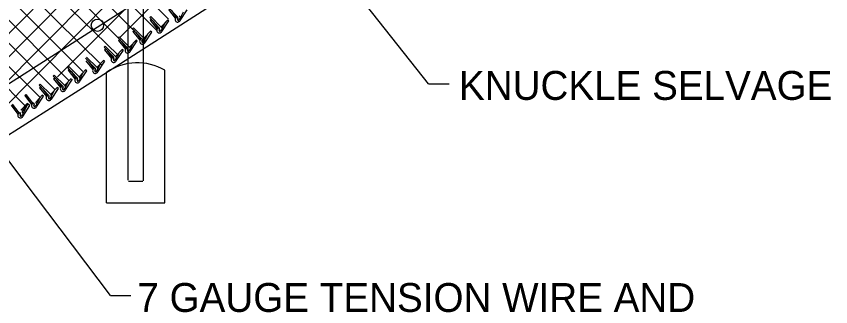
# Model space of a CAD drawing. Extents: x 0 to 2.85, y -0.1 to 1.83.
# Drawn here: x 1.7594 to 2.0414, y 1.3819 to 1.4824 of the extents above; entities that cross this region are included whole.
import ezdxf

# ---------------------------------------------------------------- set-up
doc = ezdxf.new("R2010")
doc.units = 0
for name, color, linetype in [('CT_Dimensions', 7, 'Continuous'), ('sb_Chainlink Fence', 7, 'Continuous'), ('sb_Earth', 7, 'Continuous'), ('sb_Existing Concrete', 7, 'Continuous'), ('sb_Existing Structural Steel', 7, 'Continuous')]:
    doc.layers.add(name, color=color, linetype=linetype)

msp = doc.modelspace()

# ---------------------------------------------------------------- linework, layer by layer
at = {"layer": 'CT_Dimensions'}
for p, q in [((1.9021660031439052, 1.4590312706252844), (1.8609873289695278, 1.5110686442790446)), ((1.9021660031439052, 1.4590312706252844), (1.9092764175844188, 1.4590312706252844)), ((1.7920044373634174, 1.3858294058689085), (1.74611189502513, 1.4465451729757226)), ((1.7920044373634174, 1.3858294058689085), (1.7991148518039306, 1.3858294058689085))]:
    msp.add_line(p, q, dxfattribs=at)
at = {"layer": 'sb_Chainlink Fence'}
for p, q in [((1.689092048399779, 1.4081735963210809), (1.9986754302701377, 1.720458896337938)), ((1.713665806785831, 1.4249653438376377), (1.998677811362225, 1.7124648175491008)), ((1.7334939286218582, 1.436970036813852), (1.9948211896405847, 1.700578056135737)), ((1.7532122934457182, 1.448864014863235), (1.998630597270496, 1.6964242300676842)), ((1.7736272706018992, 1.4614473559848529), (1.9971689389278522, 1.6849890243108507)), ((1.7950888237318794, 1.474947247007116), (1.9974037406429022, 1.6772621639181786)), ((1.7349460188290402, 1.558625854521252), (1.8121597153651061, 1.481412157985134)), ((1.7293783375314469, 1.5562318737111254), (1.8082147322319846, 1.4773954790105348)), ((1.727580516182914, 1.5500680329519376), (1.7997229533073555, 1.477925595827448)), ((1.7215126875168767, 1.548174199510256), (1.7947317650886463, 1.4749551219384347)), ((1.716204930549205, 1.5455202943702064), (1.7947645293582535, 1.4688543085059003)), ((1.705270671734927, 1.5405312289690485), (1.774946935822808, 1.4708549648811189)), ((1.7123356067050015, 1.5414279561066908), (1.7889703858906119, 1.4655716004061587)), ((1.7001417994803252, 1.5376984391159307), (1.7776412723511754, 1.4601989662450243)), ((1.6951924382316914, 1.5346861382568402), (1.7728832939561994, 1.4569952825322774)), ((1.6907662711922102, 1.5311506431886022), (1.7605489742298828, 1.4613679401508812)), ((1.685895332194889, 1.5280599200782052), (1.7624942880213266, 1.4514609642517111)), ((1.8151488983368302, 1.4823272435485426), (1.8119270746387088, 1.4857572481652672)), ((1.8120604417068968, 1.484831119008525), (1.8144700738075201, 1.4817938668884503)), ((1.813099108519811, 1.4844979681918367), (1.8147937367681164, 1.482186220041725)), ((1.8161694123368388, 1.4809619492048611), (1.8186097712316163, 1.4846482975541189)), ((1.8164483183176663, 1.4824171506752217), (1.8172615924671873, 1.4839678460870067)), ((1.8055949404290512, 1.4819829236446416), (1.8059911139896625, 1.4823411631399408)), ((1.808816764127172, 1.4785529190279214), (1.8055949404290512, 1.4819829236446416)), ((1.8057283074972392, 1.481056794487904), (1.8061244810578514, 1.4814150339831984)), ((1.8057283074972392, 1.481056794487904), (1.8081379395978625, 1.4780195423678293)), ((1.8096146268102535, 1.4786945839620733), (1.8059911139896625, 1.4823411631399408)), ((1.8118319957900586, 1.4811791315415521), (1.8096597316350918, 1.4788440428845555)), ((1.8118319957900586, 1.4811791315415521), (1.8096735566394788, 1.478857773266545)), ((1.8098372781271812, 1.4771876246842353), (1.812277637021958, 1.4808739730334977)), ((1.812277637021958, 1.4808739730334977), (1.8118319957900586, 1.4811791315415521)), ((1.8144815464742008, 1.4817691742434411), (1.81445043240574, 1.4816963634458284)), ((1.8145180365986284, 1.4818372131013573), (1.8144815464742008, 1.4817691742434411)), ((1.815007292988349, 1.4824139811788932), (1.8145155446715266, 1.4818351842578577)), ((1.8150138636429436, 1.4824229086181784), (1.8145180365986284, 1.4818372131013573)), ((1.8151961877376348, 1.4814335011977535), (1.8153601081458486, 1.4817876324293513)), ((1.815359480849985, 1.481775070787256), (1.8151965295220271, 1.4814415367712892)), ((1.8161225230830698, 1.4816307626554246), (1.8156768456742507, 1.481104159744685)), ((1.815717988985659, 1.4811474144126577), (1.8161225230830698, 1.4816307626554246)), ((1.7996496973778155, 1.478102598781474), (1.800045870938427, 1.4784608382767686)), ((1.8028715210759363, 1.474672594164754), (1.7996496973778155, 1.478102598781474)), ((1.8036693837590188, 1.4748142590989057), (1.800045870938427, 1.4784608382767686)), ((1.8067669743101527, 1.4807236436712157), (1.8084616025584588, 1.4784118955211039)), ((1.8081494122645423, 1.47799484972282), (1.8081182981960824, 1.4779220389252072)), ((1.80818590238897, 1.478062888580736), (1.8081494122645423, 1.47799484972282)), ((1.8086751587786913, 1.4786396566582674), (1.8081834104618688, 1.4780608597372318)), ((1.8086817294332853, 1.4786485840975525), (1.80818590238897, 1.478062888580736)), ((1.8088640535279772, 1.4776591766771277), (1.8090279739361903, 1.4780133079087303)), ((1.8090273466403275, 1.47800074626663), (1.8088643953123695, 1.4776672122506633)), ((1.8101161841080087, 1.478642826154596), (1.8109294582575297, 1.4801935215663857)), ((1.7946264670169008, 1.4750215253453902), (1.7950226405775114, 1.4753797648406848)), ((1.798646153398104, 1.471733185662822), (1.7950226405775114, 1.4753797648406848)), ((1.7997830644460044, 1.4771764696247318), (1.800179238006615, 1.4775347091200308)), ((1.7997830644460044, 1.4771764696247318), (1.8021926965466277, 1.474139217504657)), ((1.800821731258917, 1.476843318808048), (1.8025163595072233, 1.4745315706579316)), ((1.8058867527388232, 1.4772988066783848), (1.8037144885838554, 1.4749637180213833)), ((1.8058867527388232, 1.4772988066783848), (1.8037283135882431, 1.4749774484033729)), ((1.8038920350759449, 1.4733072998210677), (1.8063323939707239, 1.4769936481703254)), ((1.8041709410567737, 1.4747625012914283), (1.8049842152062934, 1.4763131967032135)), ((1.8063323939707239, 1.4769936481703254), (1.8058867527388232, 1.4772988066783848)), ((1.8097903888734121, 1.4778564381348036), (1.8093447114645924, 1.4773298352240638)), ((1.8093858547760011, 1.4773730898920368), (1.8097903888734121, 1.4778564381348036)), ((1.7978482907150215, 1.4715915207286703), (1.7946264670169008, 1.4750215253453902)), ((1.794759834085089, 1.474095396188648), (1.7951560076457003, 1.4744536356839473)), ((1.794759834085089, 1.474095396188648), (1.797169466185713, 1.4710581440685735)), ((1.7957985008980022, 1.4737622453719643), (1.7974931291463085, 1.4714504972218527)), ((1.8008635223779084, 1.474217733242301), (1.7986912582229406, 1.4718826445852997)), ((1.8008635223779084, 1.474217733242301), (1.7987050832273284, 1.4718963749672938)), ((1.7988688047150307, 1.4702262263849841), (1.801309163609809, 1.473912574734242)), ((1.7991477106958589, 1.4716814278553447), (1.7999609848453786, 1.47323212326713)), ((1.801309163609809, 1.473912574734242), (1.8008635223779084, 1.474217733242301)), ((1.8022041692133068, 1.4741145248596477), (1.802173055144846, 1.4740417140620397)), ((1.8022406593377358, 1.4741825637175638), (1.8022041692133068, 1.4741145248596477)), ((1.802729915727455, 1.4747593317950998), (1.8022381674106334, 1.4741805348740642)), ((1.802736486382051, 1.4747682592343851), (1.8022406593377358, 1.4741825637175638)), ((1.8029188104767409, 1.4737788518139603), (1.8030827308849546, 1.474132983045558)), ((1.8030821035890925, 1.4741204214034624), (1.8029191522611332, 1.4737868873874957)), ((1.8038451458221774, 1.4739761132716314), (1.8033994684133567, 1.4734495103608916)), ((1.8034406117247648, 1.4734927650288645), (1.8038451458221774, 1.4739761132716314)), ((1.7740540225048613, 1.4717105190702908), (1.782411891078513, 1.4633526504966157)), ((1.7897958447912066, 1.4717888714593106), (1.7901920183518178, 1.4721471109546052)), ((1.793017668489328, 1.4683588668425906), (1.7897958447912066, 1.4717888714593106)), ((1.7899292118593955, 1.4708627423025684), (1.7903253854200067, 1.4712209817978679)), ((1.7899292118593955, 1.4708627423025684), (1.7923388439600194, 1.4678254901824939)), ((1.7938155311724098, 1.4685005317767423), (1.7901920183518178, 1.4721471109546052)), ((1.790967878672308, 1.4705295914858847), (1.7926625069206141, 1.468217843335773)), ((1.7960329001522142, 1.4709850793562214), (1.793860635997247, 1.46864999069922)), ((1.7960329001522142, 1.4709850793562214), (1.7938744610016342, 1.4686637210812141)), ((1.7940381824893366, 1.4669935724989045), (1.796478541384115, 1.4706799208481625)), ((1.7943170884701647, 1.468448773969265), (1.795130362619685, 1.469999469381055)), ((1.796478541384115, 1.4706799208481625), (1.7960329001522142, 1.4709850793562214)), ((1.797180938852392, 1.4710334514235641), (1.7971498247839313, 1.470960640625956)), ((1.797217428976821, 1.47110149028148), (1.797180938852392, 1.4710334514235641)), ((1.7977066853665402, 1.471678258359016), (1.797214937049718, 1.4710994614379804)), ((1.7977132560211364, 1.4716871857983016), (1.797217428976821, 1.47110149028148)), ((1.797895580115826, 1.4706977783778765), (1.7980595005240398, 1.4710519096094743)), ((1.7980588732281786, 1.4710393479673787), (1.7978959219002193, 1.470705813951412)), ((1.7988219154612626, 1.4708950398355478), (1.798376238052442, 1.470368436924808)), ((1.7984173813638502, 1.4704116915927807), (1.7988219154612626, 1.4708950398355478)), ((1.7865935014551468, 1.4645487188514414), (1.7833716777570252, 1.467978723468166)), ((1.7835050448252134, 1.4670525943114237), (1.7859146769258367, 1.464015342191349)), ((1.7873913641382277, 1.4646903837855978), (1.7837678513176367, 1.4683369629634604)), ((1.7845437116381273, 1.4667194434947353), (1.786238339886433, 1.4644076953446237)), ((1.7896087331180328, 1.4671749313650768), (1.7874364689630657, 1.4648398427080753)), ((1.7896087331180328, 1.4671749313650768), (1.7874502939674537, 1.4648535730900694)), ((1.7876140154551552, 1.463183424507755), (1.7900543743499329, 1.4668697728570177)), ((1.7900543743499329, 1.4668697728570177), (1.7896087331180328, 1.4671749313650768)), ((1.7923503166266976, 1.4678007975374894), (1.7923192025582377, 1.4677279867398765)), ((1.7923868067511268, 1.4678688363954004), (1.7923503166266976, 1.4678007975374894)), ((1.792876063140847, 1.4684456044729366), (1.7923843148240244, 1.4678668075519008)), ((1.792882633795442, 1.468454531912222), (1.7923868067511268, 1.4678688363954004)), ((1.7930649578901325, 1.467465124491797), (1.7932288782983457, 1.4678192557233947)), ((1.7932282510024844, 1.467806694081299), (1.793065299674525, 1.4674731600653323)), ((1.7939912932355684, 1.4676623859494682), (1.7935456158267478, 1.467135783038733)), ((1.7935867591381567, 1.467179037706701), (1.7939912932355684, 1.4676623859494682)), ((1.7771850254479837, 1.4647243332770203), (1.7775811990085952, 1.465082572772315)), ((1.7804068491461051, 1.4612943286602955), (1.7771850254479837, 1.4647243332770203)), ((1.7773183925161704, 1.463798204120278), (1.777714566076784, 1.4641564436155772)), ((1.7812047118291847, 1.461435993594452), (1.7775811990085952, 1.465082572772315)), ((1.7834220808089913, 1.463920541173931), (1.7812498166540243, 1.4615854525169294)), ((1.7834220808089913, 1.463920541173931), (1.781263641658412, 1.4615991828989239)), ((1.7838677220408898, 1.4636153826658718), (1.7834220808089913, 1.463920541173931)), ((1.7859261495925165, 1.4639906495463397), (1.7858950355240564, 1.463917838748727)), ((1.7859626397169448, 1.464058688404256), (1.7859261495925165, 1.4639906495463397)), ((1.7864518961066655, 1.4646354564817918), (1.785960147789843, 1.4640566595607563)), ((1.78645846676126, 1.4646443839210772), (1.7859626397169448, 1.464058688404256)), ((1.7866407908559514, 1.4636549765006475), (1.7868047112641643, 1.46400910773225)), ((1.7868040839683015, 1.4639965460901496), (1.7866411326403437, 1.4636630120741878)), ((1.7875671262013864, 1.4638522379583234), (1.7871214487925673, 1.4633256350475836)), ((1.7871625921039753, 1.4633688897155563), (1.7875671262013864, 1.4638522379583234)), ((1.7878929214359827, 1.4646386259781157), (1.7887061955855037, 1.4661893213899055)), ((1.7676168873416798, 1.4542955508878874), (1.760468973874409, 1.4614889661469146)), ((1.7721778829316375, 1.4617438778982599), (1.772574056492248, 1.4621021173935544)), ((1.7753997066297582, 1.45831387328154), (1.7721778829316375, 1.4617438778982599)), ((1.7723112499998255, 1.4608177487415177), (1.7727074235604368, 1.4611759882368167)), ((1.7761975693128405, 1.4584555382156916), (1.772574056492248, 1.4621021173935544)), ((1.7773183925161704, 1.463798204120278), (1.7797280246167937, 1.4607609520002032)), ((1.7783570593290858, 1.4634650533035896), (1.7800516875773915, 1.461153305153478)), ((1.780265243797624, 1.4613810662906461), (1.7797734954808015, 1.4608022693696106)), ((1.7802718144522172, 1.4613899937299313), (1.7797759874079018, 1.4608042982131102)), ((1.7814273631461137, 1.4599290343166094), (1.7838677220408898, 1.4636153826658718)), ((1.7817062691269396, 1.46138423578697), (1.7825195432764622, 1.4629349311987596)), ((1.7672997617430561, 1.4586065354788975), (1.7676959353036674, 1.458964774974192)), ((1.7705215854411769, 1.4551765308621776), (1.7672997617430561, 1.4586065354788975)), ((1.7713194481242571, 1.4553181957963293), (1.7676959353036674, 1.458964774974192)), ((1.7723112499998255, 1.4608177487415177), (1.7747208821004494, 1.4577804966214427)), ((1.773349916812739, 1.460484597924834), (1.775044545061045, 1.4581728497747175)), ((1.775258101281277, 1.4584006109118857), (1.7747663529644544, 1.45782181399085)), ((1.775264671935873, 1.458409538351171), (1.7747688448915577, 1.4578238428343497)), ((1.7784149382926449, 1.4609400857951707), (1.7762426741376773, 1.458604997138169)), ((1.7784149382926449, 1.4609400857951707), (1.776256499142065, 1.4586187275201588)), ((1.7764202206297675, 1.4569485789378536), (1.7788605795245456, 1.4606349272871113)), ((1.7766991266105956, 1.4584037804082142), (1.777512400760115, 1.4599544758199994)), ((1.7797394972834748, 1.4607362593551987), (1.779708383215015, 1.4606634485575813)), ((1.7797759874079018, 1.4608042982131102), (1.7797394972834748, 1.4607362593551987)), ((1.7804541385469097, 1.4604005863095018), (1.7806180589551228, 1.4607547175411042)), ((1.7806174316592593, 1.4607421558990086), (1.7804544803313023, 1.4604086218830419)), ((1.7813804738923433, 1.4605978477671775), (1.7809347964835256, 1.4600712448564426)), ((1.7809759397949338, 1.4601144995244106), (1.7813804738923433, 1.4605978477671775)), ((1.7674331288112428, 1.4576804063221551), (1.7678293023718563, 1.4580386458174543)), ((1.7674331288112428, 1.4576804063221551), (1.769842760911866, 1.4546431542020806)), ((1.7684717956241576, 1.4573472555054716), (1.7701664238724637, 1.4550355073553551)), ((1.7735368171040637, 1.4578027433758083), (1.7713645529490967, 1.4554676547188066)), ((1.7735368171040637, 1.4578027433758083), (1.7713783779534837, 1.455481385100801)), ((1.7715420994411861, 1.4538112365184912), (1.7739824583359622, 1.457497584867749)), ((1.771821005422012, 1.4552664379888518), (1.7726342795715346, 1.456817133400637)), ((1.7739824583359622, 1.457497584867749), (1.7735368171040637, 1.4578027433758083)), ((1.7747323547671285, 1.4577558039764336), (1.7747012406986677, 1.4576829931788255)), ((1.7747688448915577, 1.4578238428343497), (1.7747323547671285, 1.4577558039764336)), ((1.7747920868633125, 1.4577099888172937), (1.7747609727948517, 1.457637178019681)), ((1.7748285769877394, 1.4577780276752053), (1.7747920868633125, 1.4577099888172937)), ((1.7754469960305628, 1.4574201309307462), (1.7756109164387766, 1.457774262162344)), ((1.775610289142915, 1.4577617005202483), (1.7754473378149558, 1.4574281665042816)), ((1.776373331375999, 1.4576173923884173), (1.7759276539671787, 1.4570907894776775)), ((1.7759687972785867, 1.4571340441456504), (1.776373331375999, 1.4576173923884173)), ((1.76230612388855, 1.4549912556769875), (1.7627022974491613, 1.4553494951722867)), ((1.76230612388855, 1.4549912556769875), (1.764715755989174, 1.4519540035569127)), ((1.7627022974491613, 1.4553494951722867), (1.7650394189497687, 1.4523463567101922)), ((1.7652529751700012, 1.4525741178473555), (1.7647612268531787, 1.4519953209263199)), ((1.7652595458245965, 1.4525830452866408), (1.7647637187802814, 1.4519973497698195)), ((1.7684098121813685, 1.4551135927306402), (1.7662375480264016, 1.452778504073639)), ((1.7684098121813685, 1.4551135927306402), (1.7662513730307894, 1.4527922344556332)), ((1.766415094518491, 1.4511220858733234), (1.7688554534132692, 1.4548084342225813)), ((1.76669400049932, 1.4525772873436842), (1.7675072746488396, 1.4541279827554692)), ((1.7688554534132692, 1.4548084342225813), (1.7684098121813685, 1.4551135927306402)), ((1.7696650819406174, 1.4550208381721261), (1.7696339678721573, 1.4549480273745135)), ((1.7697015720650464, 1.4550888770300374), (1.7696650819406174, 1.4550208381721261)), ((1.7698542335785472, 1.4546184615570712), (1.7698231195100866, 1.4545456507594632)), ((1.7698907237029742, 1.4546865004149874), (1.7698542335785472, 1.4546184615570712)), ((1.7703799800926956, 1.4552632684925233), (1.769888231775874, 1.4546844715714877)), ((1.7703865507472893, 1.4552721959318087), (1.7698907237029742, 1.4546865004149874)), ((1.770568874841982, 1.4542827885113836), (1.7707327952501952, 1.4546369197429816)), ((1.7707321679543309, 1.4546243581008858), (1.7705692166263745, 1.454290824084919)), ((1.7714952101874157, 1.4544800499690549), (1.7710495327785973, 1.453953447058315)), ((1.7710906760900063, 1.4539967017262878), (1.7714952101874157, 1.4544800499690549)), ((1.7575715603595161, 1.451634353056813), (1.75998119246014, 1.4485971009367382)), ((1.757967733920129, 1.4519925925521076), (1.7603048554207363, 1.4489894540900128)), ((1.763197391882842, 1.4522746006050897), (1.761025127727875, 1.4499395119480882)), ((1.763197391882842, 1.4522746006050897), (1.761038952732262, 1.4499532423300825)), ((1.7615145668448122, 1.4494327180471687), (1.7633168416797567, 1.4521551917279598)), ((1.7616805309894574, 1.447765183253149), (1.7640742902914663, 1.4516168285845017)), ((1.7619594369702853, 1.449220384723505), (1.7634528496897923, 1.45206792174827)), ((1.7640742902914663, 1.4516168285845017), (1.763197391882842, 1.4522746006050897)), ((1.7647272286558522, 1.4519293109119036), (1.7646961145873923, 1.4518565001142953)), ((1.7647637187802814, 1.4519973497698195), (1.7647272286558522, 1.4519293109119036)), ((1.765441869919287, 1.4515936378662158), (1.7656057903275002, 1.4519477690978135)), ((1.7656051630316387, 1.4519352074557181), (1.7654422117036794, 1.4516016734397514)), ((1.7663682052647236, 1.451790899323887), (1.765922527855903, 1.4512642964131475)), ((1.765963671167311, 1.4513075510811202), (1.7663682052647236, 1.451790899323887)), ((1.7599926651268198, 1.448572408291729), (1.7599615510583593, 1.4484995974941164)), ((1.7600291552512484, 1.4486404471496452), (1.7599926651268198, 1.448572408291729)), ((1.7605184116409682, 1.4492172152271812), (1.7600266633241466, 1.4486384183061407)), ((1.7605249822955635, 1.4492261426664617), (1.7600291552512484, 1.4486404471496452)), ((1.7607073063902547, 1.4482367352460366), (1.7608712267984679, 1.448590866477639)), ((1.760870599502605, 1.4485783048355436), (1.760707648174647, 1.448244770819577)), ((1.7616336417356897, 1.4484339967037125), (1.7611879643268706, 1.447907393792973)), ((1.761229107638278, 1.4479506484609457), (1.7616336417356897, 1.4484339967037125))]:
    msp.add_line(p, q, dxfattribs=at)
for centre, radius, start, end in [((1.8153314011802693, 1.4813775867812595), 0.0009354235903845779, 150.71281129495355, 333.6194641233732), ((1.8149725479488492, 1.4819473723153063), 0.0004188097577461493, 336.42296563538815, 65.09751420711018), ((1.815484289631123, 1.4813406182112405), 0.0003049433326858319, 160.6740382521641, 309.1570792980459), ((1.8154853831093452, 1.4813420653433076), 0.0003033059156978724, 162.454436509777, 320.07648952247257), ((1.8161963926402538, 1.4824615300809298), 0.0002558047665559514, 138.96114269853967, 350.00923971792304), ((1.8158528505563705, 1.4819138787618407), 0.00039099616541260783, 313.60686611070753, 52.174038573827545), ((1.8158633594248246, 1.4819143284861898), 0.00038439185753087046, 320.1413408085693, 52.94493342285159), ((1.8089992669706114, 1.4776032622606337), 0.0009354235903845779, 150.71281129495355, 333.6194641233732), ((1.8086404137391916, 1.478173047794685), 0.0004188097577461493, 336.42296563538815, 65.09751420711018), ((1.8098642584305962, 1.4786872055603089), 0.0002558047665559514, 138.96114269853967, 350.00923971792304), ((1.8095207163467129, 1.4781395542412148), 0.00039099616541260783, 313.60686611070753, 52.174038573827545), ((1.809531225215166, 1.4781400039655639), 0.00038439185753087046, 320.1413408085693, 52.94493342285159), ((1.8091521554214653, 1.4775662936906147), 0.0003049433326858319, 160.6740382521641, 309.1570792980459), ((1.8091532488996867, 1.4775677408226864), 0.0003033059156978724, 162.454436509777, 320.07648952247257), ((1.803054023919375, 1.4737229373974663), 0.0009354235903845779, 150.71281129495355, 333.6194641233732), ((1.8026951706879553, 1.4742927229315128), 0.0004188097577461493, 336.42296563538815, 65.09751420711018), ((1.803206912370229, 1.4736859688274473), 0.0003049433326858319, 160.6740382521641, 309.1570792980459), ((1.8032080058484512, 1.4736874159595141), 0.0003033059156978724, 162.454436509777, 320.07648952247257), ((1.8039190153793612, 1.4748068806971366), 0.0002558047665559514, 138.96114269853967, 350.00923971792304), ((1.803575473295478, 1.4742592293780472), 0.00039099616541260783, 313.60686611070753, 52.174038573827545), ((1.8035859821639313, 1.4742596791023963), 0.00038439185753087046, 320.1413408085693, 52.94493342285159), ((1.7980307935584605, 1.4706418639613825), 0.0009354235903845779, 150.71281129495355, 333.6194641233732), ((1.7976719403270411, 1.471211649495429), 0.0004188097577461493, 336.42296563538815, 65.09751420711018), ((1.7981836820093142, 1.4706048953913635), 0.0003049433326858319, 160.6740382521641, 309.1570792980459), ((1.7981847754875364, 1.4706063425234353), 0.0003033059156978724, 162.454436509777, 320.07648952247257), ((1.7988957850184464, 1.4717258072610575), 0.0002558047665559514, 138.96114269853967, 350.00923971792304), ((1.7985522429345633, 1.4711781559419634), 0.00039099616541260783, 313.60686611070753, 52.174038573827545), ((1.7985627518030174, 1.4711786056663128), 0.00038439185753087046, 320.1413408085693, 52.94493342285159), ((1.793200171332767, 1.467409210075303), 0.0009354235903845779, 150.71281129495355, 333.6194641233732), ((1.792841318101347, 1.4679789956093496), 0.0004188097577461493, 336.42296563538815, 65.09751420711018), ((1.7933530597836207, 1.467372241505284), 0.0003049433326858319, 160.6740382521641, 309.1570792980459), ((1.7933541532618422, 1.4673736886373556), 0.0003033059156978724, 162.454436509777, 320.07648952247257), ((1.7940651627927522, 1.4684931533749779), 0.0002558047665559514, 138.96114269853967, 350.00923971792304), ((1.7937216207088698, 1.4679455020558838), 0.00039099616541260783, 313.60686611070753, 52.174038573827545), ((1.793732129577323, 1.4679459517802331), 0.00038439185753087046, 320.1413408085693, 52.94493342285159), ((1.7867760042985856, 1.4635990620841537), 0.0009354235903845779, 150.71281129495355, 333.6194641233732), ((1.7864171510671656, 1.4641688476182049), 0.0004188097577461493, 336.42296563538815, 65.09751420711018), ((1.7876409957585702, 1.4646830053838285), 0.0002558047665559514, 138.96114269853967, 350.00923971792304), ((1.787297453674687, 1.4641353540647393), 0.00039099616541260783, 313.60686611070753, 52.174038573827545), ((1.7873079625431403, 1.4641358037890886), 0.00038439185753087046, 320.1413408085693, 52.94493342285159), ((1.7802304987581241, 1.4609144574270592), 0.0004188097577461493, 336.42296563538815, 65.09751420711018), ((1.7814543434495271, 1.461428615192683), 0.0002558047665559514, 138.96114269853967, 350.00923971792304), ((1.781110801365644, 1.4608809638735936), 0.00039099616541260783, 313.60686611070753, 52.174038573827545), ((1.7811213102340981, 1.4608814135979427), 0.00038439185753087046, 320.1413408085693, 52.94493342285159), ((1.7869288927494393, 1.4635620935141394), 0.0003049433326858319, 160.6740382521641, 309.1570792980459), ((1.7869299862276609, 1.4635635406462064), 0.0003033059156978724, 162.454436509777, 320.07648952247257), ((1.775223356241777, 1.4579340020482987), 0.0004188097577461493, 336.42296563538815, 65.09751420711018), ((1.776447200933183, 1.4584481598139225), 0.0002558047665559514, 138.96114269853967, 350.00923971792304), ((1.7761036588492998, 1.457900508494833), 0.00039099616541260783, 313.60686611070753, 52.174038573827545), ((1.7761141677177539, 1.4579009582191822), 0.00038439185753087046, 320.1413408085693, 52.94493342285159), ((1.7805893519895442, 1.4603446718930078), 0.0009354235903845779, 150.71281129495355, 333.6194641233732), ((1.7807422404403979, 1.4603077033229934), 0.0003049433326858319, 160.6740382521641, 309.1570792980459), ((1.7807433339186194, 1.4603091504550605), 0.0003033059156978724, 162.454436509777, 320.07648952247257), ((1.7715690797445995, 1.4553108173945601), 0.0002558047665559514, 138.96114269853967, 350.00923971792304), ((1.775582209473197, 1.4573642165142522), 0.0009354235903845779, 150.71281129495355, 333.6194641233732), ((1.7757350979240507, 1.4573272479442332), 0.0003049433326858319, 160.6740382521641, 309.1570792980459), ((1.775736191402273, 1.4573286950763), 0.0003033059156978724, 162.454436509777, 320.07648952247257), ((1.7664420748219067, 1.452621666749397), 0.0002558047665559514, 138.96114269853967, 350.00923971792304), ((1.7707040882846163, 1.4542268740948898), 0.0009354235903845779, 150.71281129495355, 333.6194641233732), ((1.7703452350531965, 1.4547966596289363), 0.0004188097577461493, 336.42296563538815, 65.09751420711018), ((1.7708569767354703, 1.4541899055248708), 0.0003049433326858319, 160.6740382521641, 309.1570792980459), ((1.7708580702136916, 1.4541913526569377), 0.0003033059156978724, 162.454436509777, 320.07648952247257), ((1.7712255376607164, 1.4547631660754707), 0.00039099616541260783, 313.60686611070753, 52.174038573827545), ((1.7712360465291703, 1.4547636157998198), 0.00038439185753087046, 320.1413408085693, 52.94493342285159), ((1.7655770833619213, 1.451537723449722), 0.0009354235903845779, 150.71281129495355, 333.6194641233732), ((1.7652182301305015, 1.4521075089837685), 0.0004188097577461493, 336.42296563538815, 65.09751420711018), ((1.7657299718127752, 1.4515007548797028), 0.0003049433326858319, 160.6740382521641, 309.1570792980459), ((1.7657310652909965, 1.4515022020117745), 0.0003033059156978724, 162.454436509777, 320.07648952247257), ((1.7660985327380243, 1.452074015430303), 0.00039099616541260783, 313.60686611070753, 52.174038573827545), ((1.7661090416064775, 1.452074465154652), 0.00038439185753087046, 320.1413408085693, 52.94493342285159), ((1.7608425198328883, 1.4481808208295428), 0.0009354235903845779, 150.71281129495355, 333.6194641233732), ((1.7604836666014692, 1.4487506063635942), 0.0004188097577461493, 336.42296563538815, 65.09751420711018), ((1.760995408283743, 1.4481438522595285), 0.0003049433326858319, 160.6740382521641, 309.1570792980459), ((1.7609965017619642, 1.4481452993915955), 0.0003033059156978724, 162.454436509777, 320.07648952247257), ((1.7617075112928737, 1.4492647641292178), 0.0002558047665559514, 138.96114269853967, 350.00923971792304), ((1.7613639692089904, 1.4487171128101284), 0.00039099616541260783, 313.60686611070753, 52.174038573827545), ((1.7613744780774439, 1.4487175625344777), 0.00038439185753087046, 320.1413408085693, 52.94493342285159)]:
    msp.add_arc(centre, radius, start, end, dxfattribs=at)
at = {"layer": 'sb_Earth'}
for p, q in [((1.7823436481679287, 1.4576862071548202), (1.997309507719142, 1.5957180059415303)), ((1.5044215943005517, 1.2815901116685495), (1.7823218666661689, 1.4576319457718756))]:
    msp.add_line(p, q, dxfattribs=at)
at = {"layer": 'sb_Existing Concrete'}
for p, q in [((1.7906840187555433, 1.4178091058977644), (1.7906791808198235, 1.4630323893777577)), ((1.8108470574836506, 1.417870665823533), (1.8108899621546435, 1.4637371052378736)), ((1.7906840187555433, 1.4178091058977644), (1.8108470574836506, 1.417870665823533))]:
    msp.add_line(p, q, dxfattribs=at)
msp.add_arc((1.8013339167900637, 1.4476298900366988), 0.01872859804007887, 59.32030537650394, 124.6736909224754, dxfattribs=at)
at = {"layer": 'sb_Existing Structural Steel'}
for p, q in [((1.7742550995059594, 1.4702761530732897), (1.9983734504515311, 1.614204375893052)), ((1.7981557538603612, 1.4720658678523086), (1.7982827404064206, 1.6073621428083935)), ((1.8034024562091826, 1.4755320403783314), (1.803566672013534, 1.6074162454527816)), ((1.8034293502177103, 1.4254468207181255), (1.8034024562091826, 1.4755320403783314)), ((1.5021906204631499, 1.296704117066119), (1.7742550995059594, 1.4702761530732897)), ((1.798181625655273, 1.4256947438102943), (1.7981557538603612, 1.4720658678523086)), ((1.7600728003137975, 1.4611307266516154), (1.760468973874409, 1.4614889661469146)), ((1.7983041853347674, 1.425416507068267), (1.8032818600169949, 1.425416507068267))]:
    msp.add_line(p, q, dxfattribs=at)
msp.add_circle((1.7875017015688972, 1.4793540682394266), 0.0021204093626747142, dxfattribs=at)

# ---------------------------------------------------------------- texts
at = {"layer": 'CT_Dimensions'}
for s, p in [('KNUCKLE SELVAGE', (1.9127067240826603, 1.4535106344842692)), ('7 GAUGE TENSION WIRE AND', (1.801334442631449, 1.3800917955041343))]:
    msp.add_text(s, height=0.01, dxfattribs=at).set_placement(p)

doc.saveas('drawing.dxf')
